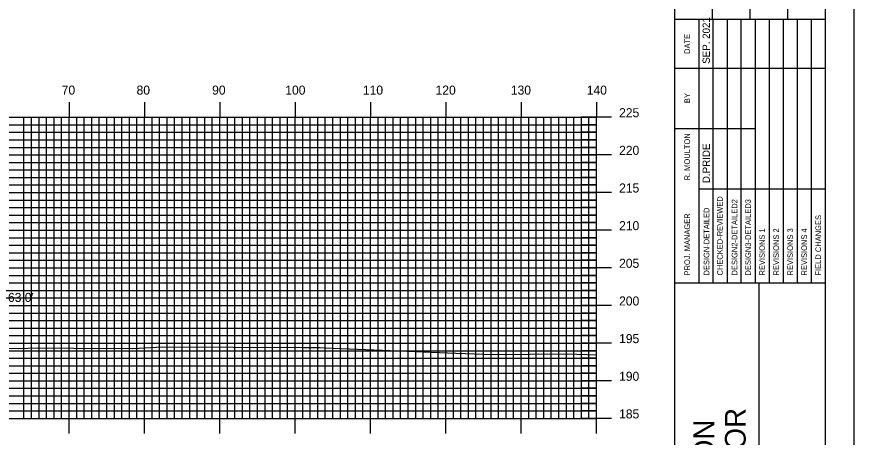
# Model space of a CAD drawing. Extents: x 1811374 to 1811717, y 442591 to 442811.
# Drawn here: x 1811602.4 to 1811713.6, y 442666.2 to 442722 of the extents above; entities that cross this region are included whole.
import ezdxf

# ---------------------------------------------------------------- set-up
doc = ezdxf.new("R2010")
doc.units = 0
for name, color, linetype in [('BORDER', 7, 'Continuous'), ('D_Text_Standard', 7, 'Continuous'), ('H_V ANNOTATION', 7, 'Continuous'), ('MAJOR', 7, 'Continuous'), ('MINOR', 7, 'Continuous'), ('PLOT BOUNDARY', 7, 'Continuous'), ('S_Roadway_Centerline', 7, 'Continuous')]:
    doc.layers.add(name, color=color, linetype=linetype)

msp = doc.modelspace()

# ---------------------------------------------------------------- linework, layer by layer
at = {"layer": 'BORDER'}
for p, q in [((1811689.8, 442596.67), (1811689.8, 442806.67)), ((1811694.8, 442721.67), (1811694.8, 442738.97)), ((1811699.8, 442721.67), (1811699.8, 442738.97)), ((1811704.8, 442721.67), (1811704.8, 442738.97)), ((1811689.8, 442721.67), (1811709.8, 442721.67)), ((1811689.8, 442686.67), (1811709.8, 442686.67)), ((1811700.98, 442616.67), (1811700.98, 442686.67))]:
    msp.add_line(p, q, dxfattribs=at)
msp.add_lwpolyline([(1811389.8, 442596.67), (1811709.8, 442596.67), (1811709.8, 442806.67), (1811389.8, 442806.67)], close=True, dxfattribs=at)
for points in [[(1811693.03, 442715.17), (1811693.03, 442721.67)], [(1811694.9, 442686.68), (1811694.9, 442721.67)], [(1811696.76, 442721.67), (1811696.76, 442686.68)], [(1811698.62, 442686.68), (1811698.62, 442721.67)], [(1811700.49, 442686.68), (1811700.49, 442721.67)], [(1811702.35, 442686.68), (1811702.35, 442721.67)], [(1811704.21, 442686.68), (1811704.21, 442721.67)], [(1811706.08, 442686.68), (1811706.08, 442721.67)], [(1811707.94, 442686.68), (1811707.94, 442721.67)], [(1811693.03, 442686.68), (1811693.03, 442720.26)], [(1811689.8, 442715.17), (1811709.8, 442715.17)], [(1811689.8, 442707.17), (1811693.03, 442707.17)], [(1811693.03, 442707.17), (1811700.49, 442707.17)], [(1811693.03, 442699.17), (1811709.8, 442699.17)]]:
    msp.add_lwpolyline(points, dxfattribs=at)
at = {"layer": 'MAJOR'}
for p, q in [((1811609.4, 442710.67), (1811609.4, 442708.67)), ((1811619.4, 442710.67), (1811619.4, 442708.67)), ((1811629.4, 442710.67), (1811629.4, 442708.67)), ((1811639.4, 442710.67), (1811639.4, 442708.67)), ((1811649.4, 442710.67), (1811649.4, 442708.67)), ((1811659.4, 442710.67), (1811659.4, 442708.67)), ((1811669.4, 442710.67), (1811669.4, 442708.67)), ((1811679.4, 442710.67), (1811679.4, 442708.67)), ((1811399.4, 442708.67), (1811679.4, 442708.67)), ((1811399.4, 442708.67), (1811679.4, 442708.67)), ((1811609.4, 442668.67), (1811609.4, 442708.67)), ((1811619.4, 442668.67), (1811619.4, 442708.67)), ((1811629.4, 442668.67), (1811629.4, 442708.67)), ((1811639.4, 442668.67), (1811639.4, 442708.67)), ((1811649.4, 442668.67), (1811649.4, 442708.67)), ((1811659.4, 442668.67), (1811659.4, 442708.67)), ((1811669.4, 442668.67), (1811669.4, 442708.67)), ((1811681.41, 442708.67), (1811677.4, 442708.67)), ((1811679.4, 442668.67), (1811679.4, 442708.67)), ((1811679.4, 442668.67), (1811679.4, 442708.67)), ((1811399.4, 442703.67), (1811679.4, 442703.67)), ((1811681.41, 442703.67), (1811677.4, 442703.67)), ((1811399.4, 442698.67), (1811679.4, 442698.67)), ((1811681.41, 442698.67), (1811677.4, 442698.67)), ((1811399.4, 442693.67), (1811679.4, 442693.67)), ((1811681.41, 442693.67), (1811677.4, 442693.67)), ((1811399.4, 442688.67), (1811679.4, 442688.67)), ((1811681.41, 442688.67), (1811677.4, 442688.67)), ((1811399.4, 442683.67), (1811679.4, 442683.67)), ((1811681.41, 442683.67), (1811677.4, 442683.67)), ((1811399.4, 442678.67), (1811679.4, 442678.67)), ((1811681.41, 442678.67), (1811677.4, 442678.67)), ((1811399.4, 442673.67), (1811679.4, 442673.67)), ((1811681.41, 442673.67), (1811677.4, 442673.67)), ((1811399.4, 442668.67), (1811679.4, 442668.67)), ((1811399.4, 442668.67), (1811679.4, 442668.67)), ((1811609.4, 442666.66), (1811609.4, 442668.67)), ((1811619.4, 442666.66), (1811619.4, 442668.67)), ((1811629.4, 442666.66), (1811629.4, 442668.67)), ((1811639.4, 442666.66), (1811639.4, 442668.67)), ((1811649.4, 442666.66), (1811649.4, 442668.67)), ((1811659.4, 442666.66), (1811659.4, 442668.67)), ((1811669.4, 442666.66), (1811669.4, 442668.67)), ((1811681.41, 442668.67), (1811677.4, 442668.67)), ((1811679.4, 442666.66), (1811679.4, 442668.67))]:
    msp.add_line(p, q, dxfattribs=at)
at = {"layer": 'MINOR'}
for p, q in [((1811399.4, 442707.67), (1811679.4, 442707.67)), ((1811603.4, 442668.67), (1811603.4, 442708.67)), ((1811604.4, 442668.67), (1811604.4, 442708.67)), ((1811605.4, 442668.67), (1811605.4, 442708.67)), ((1811606.4, 442668.67), (1811606.4, 442708.67)), ((1811607.4, 442668.67), (1811607.4, 442708.67)), ((1811608.4, 442668.67), (1811608.4, 442708.67)), ((1811610.4, 442668.67), (1811610.4, 442708.67)), ((1811611.4, 442668.67), (1811611.4, 442708.67)), ((1811612.4, 442668.67), (1811612.4, 442708.67)), ((1811613.4, 442668.67), (1811613.4, 442708.67)), ((1811614.4, 442668.67), (1811614.4, 442708.67)), ((1811615.4, 442668.67), (1811615.4, 442708.67)), ((1811616.4, 442668.67), (1811616.4, 442708.67)), ((1811617.4, 442668.67), (1811617.4, 442708.67)), ((1811618.4, 442668.67), (1811618.4, 442708.67)), ((1811620.4, 442668.67), (1811620.4, 442708.67)), ((1811621.4, 442668.67), (1811621.4, 442708.67)), ((1811622.4, 442668.67), (1811622.4, 442708.67)), ((1811623.4, 442668.67), (1811623.4, 442708.67)), ((1811624.4, 442668.67), (1811624.4, 442708.67)), ((1811625.4, 442668.67), (1811625.4, 442708.67)), ((1811626.4, 442668.67), (1811626.4, 442708.67)), ((1811627.4, 442668.67), (1811627.4, 442708.67)), ((1811628.4, 442668.67), (1811628.4, 442708.67)), ((1811630.4, 442668.67), (1811630.4, 442708.67)), ((1811631.4, 442668.67), (1811631.4, 442708.67)), ((1811632.4, 442668.67), (1811632.4, 442708.67)), ((1811633.4, 442668.67), (1811633.4, 442708.67)), ((1811634.4, 442668.67), (1811634.4, 442708.67)), ((1811635.4, 442668.67), (1811635.4, 442708.67)), ((1811636.4, 442668.67), (1811636.4, 442708.67)), ((1811637.4, 442668.67), (1811637.4, 442708.67)), ((1811638.4, 442668.67), (1811638.4, 442708.67)), ((1811640.4, 442668.67), (1811640.4, 442708.67)), ((1811641.4, 442668.67), (1811641.4, 442708.67)), ((1811642.4, 442668.67), (1811642.4, 442708.67)), ((1811643.4, 442668.67), (1811643.4, 442708.67)), ((1811644.4, 442668.67), (1811644.4, 442708.67)), ((1811645.4, 442668.67), (1811645.4, 442708.67)), ((1811646.4, 442668.67), (1811646.4, 442708.67)), ((1811647.4, 442668.67), (1811647.4, 442708.67)), ((1811648.4, 442668.67), (1811648.4, 442708.67)), ((1811650.4, 442668.67), (1811650.4, 442708.67)), ((1811651.4, 442668.67), (1811651.4, 442708.67)), ((1811652.4, 442668.67), (1811652.4, 442708.67)), ((1811653.4, 442668.67), (1811653.4, 442708.67)), ((1811654.4, 442668.67), (1811654.4, 442708.67)), ((1811655.4, 442668.67), (1811655.4, 442708.67)), ((1811656.4, 442668.67), (1811656.4, 442708.67)), ((1811657.4, 442668.67), (1811657.4, 442708.67)), ((1811658.4, 442668.67), (1811658.4, 442708.67)), ((1811660.4, 442668.67), (1811660.4, 442708.67)), ((1811661.4, 442668.67), (1811661.4, 442708.67)), ((1811662.4, 442668.67), (1811662.4, 442708.67)), ((1811663.4, 442668.67), (1811663.4, 442708.67)), ((1811664.4, 442668.67), (1811664.4, 442708.67)), ((1811665.4, 442668.67), (1811665.4, 442708.67)), ((1811666.4, 442668.67), (1811666.4, 442708.67)), ((1811667.4, 442668.67), (1811667.4, 442708.67)), ((1811668.4, 442668.67), (1811668.4, 442708.67)), ((1811670.4, 442668.67), (1811670.4, 442708.67)), ((1811671.4, 442668.67), (1811671.4, 442708.67)), ((1811672.4, 442668.67), (1811672.4, 442708.67)), ((1811673.4, 442668.67), (1811673.4, 442708.67)), ((1811674.4, 442668.67), (1811674.4, 442708.67)), ((1811675.4, 442668.67), (1811675.4, 442708.67)), ((1811676.4, 442668.67), (1811676.4, 442708.67)), ((1811677.4, 442668.67), (1811677.4, 442708.67)), ((1811679.4, 442707.67), (1811677.4, 442707.67)), ((1811678.4, 442668.67), (1811678.4, 442708.67)), ((1811399.4, 442706.67), (1811679.4, 442706.67)), ((1811679.4, 442706.67), (1811677.4, 442706.67)), ((1811399.4, 442705.67), (1811679.4, 442705.67)), ((1811679.4, 442705.67), (1811677.4, 442705.67)), ((1811399.4, 442704.67), (1811679.4, 442704.67)), ((1811679.4, 442704.67), (1811677.4, 442704.67)), ((1811399.4, 442702.67), (1811679.4, 442702.67)), ((1811679.4, 442702.67), (1811677.4, 442702.67)), ((1811399.4, 442701.67), (1811679.4, 442701.67)), ((1811679.4, 442701.67), (1811677.4, 442701.67)), ((1811399.4, 442700.67), (1811679.4, 442700.67)), ((1811679.4, 442700.67), (1811677.4, 442700.67)), ((1811399.4, 442699.67), (1811679.4, 442699.67)), ((1811679.4, 442699.67), (1811677.4, 442699.67)), ((1811399.4, 442697.67), (1811679.4, 442697.67)), ((1811679.4, 442697.67), (1811677.4, 442697.67)), ((1811399.4, 442696.67), (1811679.4, 442696.67)), ((1811679.4, 442696.67), (1811677.4, 442696.67)), ((1811399.4, 442695.67), (1811679.4, 442695.67)), ((1811679.4, 442695.67), (1811677.4, 442695.67)), ((1811399.4, 442694.67), (1811679.4, 442694.67)), ((1811679.4, 442694.67), (1811677.4, 442694.67)), ((1811399.4, 442692.67), (1811679.4, 442692.67)), ((1811679.4, 442692.67), (1811677.4, 442692.67)), ((1811399.4, 442691.67), (1811679.4, 442691.67)), ((1811679.4, 442691.67), (1811677.4, 442691.67)), ((1811399.4, 442690.67), (1811679.4, 442690.67)), ((1811679.4, 442690.67), (1811677.4, 442690.67)), ((1811399.4, 442689.67), (1811679.4, 442689.67)), ((1811679.4, 442689.67), (1811677.4, 442689.67)), ((1811399.4, 442687.67), (1811679.4, 442687.67)), ((1811679.4, 442687.67), (1811677.4, 442687.67)), ((1811399.4, 442686.67), (1811679.4, 442686.67)), ((1811679.4, 442686.67), (1811677.4, 442686.67)), ((1811399.4, 442685.67), (1811679.4, 442685.67)), ((1811679.4, 442685.67), (1811677.4, 442685.67)), ((1811399.4, 442684.67), (1811679.4, 442684.67)), ((1811679.4, 442684.67), (1811677.4, 442684.67)), ((1811399.4, 442682.67), (1811679.4, 442682.67)), ((1811679.4, 442682.67), (1811677.4, 442682.67)), ((1811399.4, 442681.67), (1811679.4, 442681.67)), ((1811679.4, 442681.67), (1811677.4, 442681.67)), ((1811399.4, 442680.67), (1811679.4, 442680.67)), ((1811679.4, 442680.67), (1811677.4, 442680.67)), ((1811399.4, 442679.67), (1811679.4, 442679.67)), ((1811679.4, 442679.67), (1811677.4, 442679.67)), ((1811399.4, 442677.67), (1811679.4, 442677.67)), ((1811679.4, 442677.67), (1811677.4, 442677.67)), ((1811399.4, 442676.67), (1811679.4, 442676.67)), ((1811679.4, 442676.67), (1811677.4, 442676.67)), ((1811399.4, 442675.67), (1811679.4, 442675.67)), ((1811679.4, 442675.67), (1811677.4, 442675.67)), ((1811399.4, 442674.67), (1811679.4, 442674.67)), ((1811679.4, 442674.67), (1811677.4, 442674.67)), ((1811399.4, 442672.67), (1811679.4, 442672.67)), ((1811679.4, 442672.67), (1811677.4, 442672.67)), ((1811399.4, 442671.67), (1811679.4, 442671.67)), ((1811679.4, 442671.67), (1811677.4, 442671.67)), ((1811399.4, 442670.67), (1811679.4, 442670.67)), ((1811679.4, 442670.67), (1811677.4, 442670.67)), ((1811399.4, 442669.67), (1811679.4, 442669.67)), ((1811679.4, 442669.67), (1811677.4, 442669.67))]:
    msp.add_line(p, q, dxfattribs=at)
at = {"layer": 'PLOT BOUNDARY'}
msp.add_lwpolyline([(1811373.62, 442590.55), (1811713.62, 442590.55), (1811713.62, 442810.55), (1811373.62, 442810.55)], close=True, dxfattribs=at)
at = {"layer": 'S_Roadway_Centerline'}
msp.add_lwpolyline([(1811590.01, 442678.19), (1811602.72, 442677.97), (1811605.14, 442678.04), (1811610.01, 442678.01), (1811617.84, 442677.96), (1811621.79, 442678.19), (1811640.54, 442678.08), (1811642.69, 442678.08), (1811643.35, 442678.05), (1811660.73, 442677.36), (1811665.68, 442677.14), (1811675.53, 442677.25), (1811679.4, 442677.13)], dxfattribs=at)

# ---------------------------------------------------------------- texts
at = {"layer": 'BORDER'}
for s, height, p in [('SEP. 2021', 0.969, (1811694.45, 442715.76)), ('DATE', 0.743, (1811691.81, 442717.08)), ('BY', 0.743, (1811691.81, 442710.54)), ('R. MOULTON', 0.745, (1811691.81, 442700.28)), ('D.PRIDE', 0.969, (1811694.45, 442699.92)), ('CHECKED-REVIEWED', 0.7455, (1811696.16, 442687.65)), ('DESIGN2-DETAILED2', 0.7455, (1811698.1, 442687.65)), ('DESIGN3-DETAILED3', 0.7455, (1811699.89, 442687.65)), ('DESIGN-DETAILED', 0.7455, (1811694.38, 442687.65)), ('PROJ. MANAGER', 0.7455, (1811691.81, 442687.65)), ('FIELD CHANGES', 0.7455, (1811709.21, 442687.65)), ('REVISIONS 1', 0.7455, (1811701.75, 442687.65)), ('REVISIONS 2', 0.7455, (1811703.62, 442687.65)), ('REVISIONS 3', 0.7455, (1811705.48, 442687.65)), ('REVISIONS 4', 0.7455, (1811707.34, 442687.65)), ('1-395/ROUTE 9 CONNECTOR', 2.7557, (1811699.21, 442618.87)), ('BREWER TO EDDINGTON', 2.7557, (1811695.03, 442623.07))]:
    msp.add_text(s, height=height, rotation=90, dxfattribs=at).set_placement(p)
at = {"layer": 'D_Text_Standard'}
msp.add_text("63.0'", height=1.2, dxfattribs=at).set_placement((1811601.28, 442684.14))
at = {"layer": 'H_V ANNOTATION'}
for s, p in [('70', (1811608.41, 442711.67)), ('80', (1811618.35, 442711.67)), ('90', (1811628.38, 442711.67)), ('100', (1811638.09, 442711.67)), ('110', (1811648.39, 442711.67)), ('120', (1811658.04, 442711.67)), ('130', (1811668.03, 442711.67)), ('140', (1811678.11, 442711.67)), ('225', (1811682.4, 442708.67)), ('220', (1811682.4, 442703.67)), ('215', (1811682.4, 442698.67)), ('210', (1811682.4, 442693.67)), ('205', (1811682.4, 442688.67)), ('200', (1811682.4, 442683.67)), ('195', (1811682.4, 442678.67)), ('190', (1811682.4, 442673.67)), ('185', (1811682.4, 442668.67))]:
    msp.add_text(s, height=1.2, dxfattribs=at).set_placement(p)

doc.saveas('drawing.dxf')
